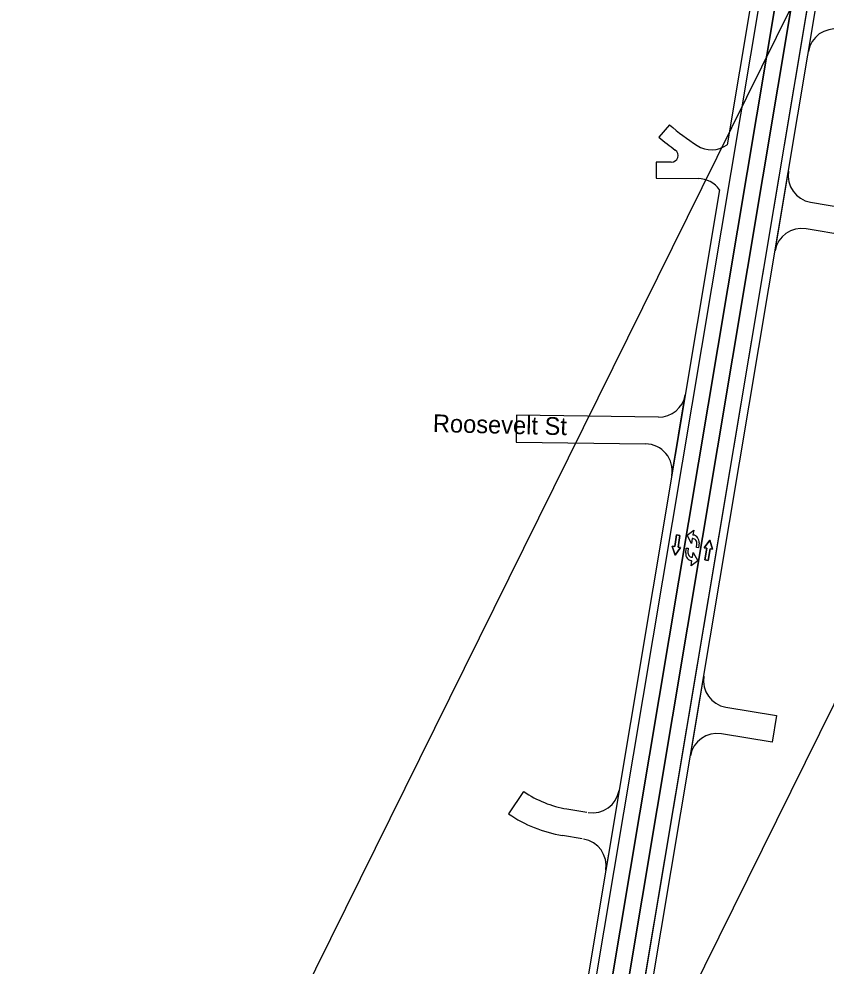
# Model space of a CAD drawing. Extents: x 14097936 to 14128734, y 8632000 to 8683104.
# Drawn here: x 14118632 to 14119231, y 8669393 to 8670096 of the extents above; entities that cross this region are included whole.
import ezdxf

# ---------------------------------------------------------------- set-up
doc = ezdxf.new("R2010")
doc.units = 0
for name, color, linetype in [('Cell', 7, 'Continuous'), ('dsn_stg_shd_prev', 7, 'Continuous'), ('dsnNonPlotable', 7, 'Continuous'), ('dsnPaintExistingEdgeLineRightWhite', 7, 'Continuous'), ('dsnPaintExistingNoPassingYellow', 7, 'Continuous'), ('dsnShadingPaved', 7, 'Continuous'), ('dsnStgShadingPropPav', 7, 'Continuous'), ('dsnTextFinalPlan', 7, 'Continuous'), ('Level 2', 7, 'Continuous'), ('Level 5', 7, 'Continuous')]:
    doc.layers.add(name, color=color, linetype=linetype)

msp = doc.modelspace()

# ---------------------------------------------------------------- linework, layer by layer
at = {"layer": 'Cell'}
for p, q in [((14119131.82, 8669710.26), (14119131.51, 8669710.3)), ((14119131.92, 8669712.89), (14119132.11, 8669712.87)), ((14119131.3, 8669696.36), (14119131.61, 8669696.32)), ((14119131.19, 8669693.72), (14119131.01, 8669693.74))]:
    msp.add_line(p, q, dxfattribs=at)
for points in [[(14119127.59, 8669712.84), (14119132.51, 8669716.53), (14119131.92, 8669712.89)], [(14119127.59, 8669712.84), (14119132.51, 8669716.53), (14119131.92, 8669712.89)], [(14119131.51, 8669710.3), (14119130.92, 8669706.66), (14119127.59, 8669712.84)], [(14119131.51, 8669710.3), (14119130.92, 8669706.66), (14119127.59, 8669712.84)], [(14119131.82, 8669710.26), (14119131.51, 8669710.3)], [(14119131.92, 8669712.89), (14119132.11, 8669712.87)], [(14119126.64, 8669699.51), (14119127.04, 8669703.17), (14119128.52, 8669703.01), (14119128.24, 8669700.4)], [(14119126.64, 8669699.51), (14119127.04, 8669703.17), (14119128.52, 8669703.01), (14119128.24, 8669700.4)], [(14119136.48, 8669707.1), (14119136.07, 8669703.44), (14119134.59, 8669703.61), (14119134.88, 8669706.22)], [(14119136.48, 8669707.1), (14119136.07, 8669703.44), (14119134.59, 8669703.61), (14119134.88, 8669706.22)], [(14119131.3, 8669696.36), (14119131.61, 8669696.32)], [(14119131.61, 8669696.32), (14119132.2, 8669699.96), (14119135.52, 8669693.77)], [(14119131.61, 8669696.32), (14119132.2, 8669699.96), (14119135.52, 8669693.77)], [(14119135.52, 8669693.77), (14119130.6, 8669690.09), (14119131.19, 8669693.72)], [(14119135.52, 8669693.77), (14119130.6, 8669690.09), (14119131.19, 8669693.72)], [(14119131.19, 8669693.72), (14119131.01, 8669693.74)]]:
    msp.add_lwpolyline(points, dxfattribs=at)
for centre, major_axis in [((14119131.41, 8669706.6), (-0.4, -3.66)), ((14119131.41, 8669706.6), (-0.4, -3.66)), ((14119131.53, 8669707.65), (-0.58, -5.22)), ((14119131.53, 8669707.65), (-0.58, -5.22)), ((14119131.59, 8669698.97), (0.58, 5.22)), ((14119131.59, 8669698.97), (0.58, 5.22)), ((14119131.7, 8669700.01), (0.4, 3.66)), ((14119131.7, 8669700.01), (0.4, 3.66))]:
    msp.add_ellipse(centre, major_axis=major_axis, ratio=0.9474, start_param=1.570796, end_param=3.141593, dxfattribs=at)
at = {"layer": 'dsn_stg_shd_prev'}
for p, q in [((14119060.64, 8669134.39), (14119230.09, 8670146.06)), ((14119178.59, 8670129.16), (14119157.36, 8670002.37)), ((14119217.64, 8670071.7), (14119227.55, 8670130.88)), ((14119114.56, 8670017.23), (14119106.77, 8670008.1)), ((14119104.75, 8669989.61), (14119104.64, 8669977.61)), ((14119115.86, 8669989.52), (14119104.75, 8669989.61)), ((14119104.64, 8669977.61), (14119135.8, 8669977.34)), ((14119192.91, 8669923.76), (14119202.82, 8669982.93)), ((14119151.79, 8669969.11), (14119013.3, 8669142.32)), ((14119219.24, 8669959.9), (14119248.83, 8669954.95)), ((14119245.53, 8669935.22), (14119216.04, 8669940.16)), ((14119116.28, 8669757.14), (14119126.31, 8669817.01)), ((14119001.11, 8669801.75), (14119000.84, 8669781.76)), ((14119106.31, 8669800.32), (14119001.11, 8669801.75)), ((14119000.84, 8669781.76), (14119096.83, 8669780.44)), ((14119130.09, 8669548.99), (14119140, 8669608.16)), ((14119156.42, 8669585.13), (14119194.02, 8669578.83)), ((14119194.02, 8669578.83), (14119190.71, 8669559.11)), ((14119190.71, 8669559.11), (14119153.11, 8669565.41)), ((14118995.18, 8669505.9), (14119006.45, 8669522.42)), ((14119077.13, 8669523.38), (14119067.22, 8669464.21)), ((14119038.32, 8669509.6), (14119053.13, 8669507.12)), ((14119049.83, 8669487.4), (14119035.02, 8669489.88))]:
    msp.add_line(p, q, dxfattribs=at)
for centre, radius, start, end in [((14119237.36, 8670068.4), 20, 80.49147, 170.49147), ((14119240.4, 8670164.87), 194, 229.55685, 237.10742), ((14119240.4, 8670164.87), 206, 229.55685, 233.84057), ((14119115.9, 8669994.52), 5, 269.49147, 53.84057), ((14119145.91, 8670018.77), 20, 237.10742, 304.91847), ((14119135.62, 8669957.34), 20, 36.06446, 89.49147), ((14119222.55, 8669979.63), 20, 170.49147, 260.49147), ((14119212.64, 8669920.45), 20, 80.49147, 170.49147), ((14119106.58, 8669820.31), 20, 269.21647, 350.49147), ((14119096.56, 8669760.45), 20, 350.49147, 89.21647), ((14119159.72, 8669604.86), 20, 170.49147, 260.49147), ((14119149.81, 8669545.68), 20, 80.49147, 170.49147), ((14119051.53, 8669588.5), 80, 235.69513, 260.49147), ((14119057.4, 8669526.69), 20, 260.49147, 350.49147), ((14119051.53, 8669588.5), 100, 235.69513, 260.49147), ((14119047.49, 8669467.51), 20, 350.49147, 80.49147)]:
    msp.add_arc(centre, radius, start, end, dxfattribs=at)
at = {"layer": 'dsnNonPlotable'}
for points in [[(14118631.64, 8668945.1), (14119326.37, 8670350.23), (14120231.75, 8669902.59), (14119537.02, 8668497.46)], [(14119315.27, 8668607.09), (14120010, 8670012.23), (14119557.31, 8670236.05), (14118862.58, 8668830.91)]]:
    msp.add_lwpolyline(points, close=True, dxfattribs=at)
at = {"layer": 'dsnPaintExistingEdgeLineRightWhite'}
msp.add_line((14119184.51, 8670128.17), (14119019.22, 8669141.32), dxfattribs=at)
msp.add_line((14119184.51, 8670128.17), (14119019.22, 8669141.32), dxfattribs=at)
msp.add_lwpolyline([(14119029.87, 8669002.67), (14119054.72, 8669135.38), (14119224.18, 8670147.05)], dxfattribs=at)
msp.add_lwpolyline([(14119029.87, 8669002.67), (14119054.72, 8669135.38), (14119224.18, 8670147.05)], dxfattribs=at)
at = {"layer": 'dsnPaintExistingNoPassingYellow'}
for p, q in [((14119031.05, 8669139.34), (14119200.51, 8670151.01)), ((14119212.34, 8670149.03), (14119042.89, 8669137.36))]:
    msp.add_line(p, q, dxfattribs=at)
at = {"layer": 'dsnShadingPaved'}
for p, q in [((14119188.67, 8670153), (14119019.22, 8669141.32)), ((14119200.51, 8670151.01), (14119031.05, 8669139.34)), ((14119031.05, 8669139.34), (14119200.51, 8670151.01)), ((14119212.34, 8670149.03), (14119042.89, 8669137.36)), ((14119042.89, 8669137.36), (14119212.34, 8670149.03)), ((14119054.72, 8669135.38), (14119224.18, 8670147.05))]:
    msp.add_line(p, q, dxfattribs=at)
at = {"layer": 'dsnStgShadingPropPav'}
for p, q in [((14119060.64, 8669134.39), (14119230.09, 8670146.06)), ((14119178.59, 8670129.16), (14119157.36, 8670002.37)), ((14119114.56, 8670017.23), (14119106.77, 8670008.1)), ((14119104.75, 8669989.61), (14119104.64, 8669977.61)), ((14119115.86, 8669989.52), (14119104.75, 8669989.61)), ((14119104.64, 8669977.61), (14119135.8, 8669977.34)), ((14119151.79, 8669969.11), (14119013.3, 8669142.32))]:
    msp.add_line(p, q, dxfattribs=at)
for centre, radius, start, end in [((14119240.4, 8670164.87), 194, 229.55685, 237.10742), ((14119240.4, 8670164.87), 206, 229.55685, 233.84057), ((14119115.9, 8669994.52), 5, 269.49147, 53.84057), ((14119145.91, 8670018.77), 20, 237.10742, 304.91847), ((14119135.62, 8669957.34), 20, 36.06446, 89.49147)]:
    msp.add_arc(centre, radius, start, end, dxfattribs=at)
at = {"layer": 'Level 2'}
for points in [[(14119122.29, 8669712.56), (14119119.82, 8669712.95), (14119118.46, 8669704.31), (14119116.61, 8669704.6), (14119118.72, 8669697.94), (14119122.78, 8669703.63), (14119120.93, 8669703.92)], [(14119140.89, 8669694.46), (14119143.36, 8669694.07), (14119144.72, 8669702.72), (14119146.57, 8669702.42), (14119144.46, 8669709.08), (14119140.4, 8669703.4), (14119142.25, 8669703.11)]]:
    msp.add_lwpolyline(points, close=True, dxfattribs=at)
at = {"layer": 'Level 5'}
for points in [[(14119120.93, 8669703.92), (14119122.78, 8669703.63), (14119118.72, 8669697.94), (14119116.61, 8669704.6), (14119118.46, 8669704.31), (14119119.82, 8669712.95), (14119122.29, 8669712.56), (14119120.93, 8669703.92)], [(14119142.25, 8669703.11), (14119140.4, 8669703.4), (14119144.46, 8669709.08), (14119146.57, 8669702.42), (14119144.72, 8669702.72), (14119143.36, 8669694.07), (14119140.89, 8669694.46), (14119142.25, 8669703.11)]]:
    msp.add_lwpolyline(points, dxfattribs=at)

# ---------------------------------------------------------------- texts
at = {"layer": 'dsnTextFinalPlan'}
msp.add_text('Roosevelt St', height=13.125, rotation=358.6374, dxfattribs=at).set_placement((14118938.8, 8669789.31))

doc.saveas('drawing.dxf')
